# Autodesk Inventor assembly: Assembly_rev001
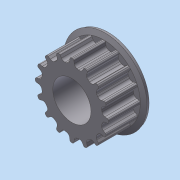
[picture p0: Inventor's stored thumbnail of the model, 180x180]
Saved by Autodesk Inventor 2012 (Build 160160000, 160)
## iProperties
Created: 2011-12
Part Number: Assembly_rev001
Document SubType Name: Assembly
Designer: Alex
Mass: 8.89187 g
Surface Area: 31.5234 cm^2
Volume: 3.28113 cm^3
Density: 2.71 g/cm^3
Author: Alex
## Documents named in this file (3)
- C:\Users\Owner\Documents\Robotics\Mechanical Design\Parts\pulley\HTD\16\HTD 5mm 16 Tooth rev001 Assembly.iam
- C:\Users\Owner\Documents\Robotics\Mechanical Design\Parts\pulley\HTD\16\HTD 5mm 16 Tooth rev001 step 2.ipt
- C:\Users\Owner\Documents\Robotics\Mechanical Design\Parts\pulley\HTD\16\Flange_rev001.ipt
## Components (2 placed, 2 different names)
1. HTD 5mm 16 Tooth rev001 step 2:1 — Insert:1
2. Flange_rev001:1 — Insert:1
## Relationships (1: Insert 1)
- Insert:1: HTD 5mm 16 Tooth rev001 step 2:1 ↔ Flange_rev001:1
